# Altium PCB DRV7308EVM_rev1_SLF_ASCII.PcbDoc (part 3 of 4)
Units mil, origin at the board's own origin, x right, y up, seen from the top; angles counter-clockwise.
Board outline 6187 x 6000 mil, 4 copper layers (Top Layer, Ground, Power, Bottom Layer), stack 61.2 mil thick; 306 components, 128 nets, 676 pads, 1026 vias.
Unrouted connection lines stored in the file: 208.
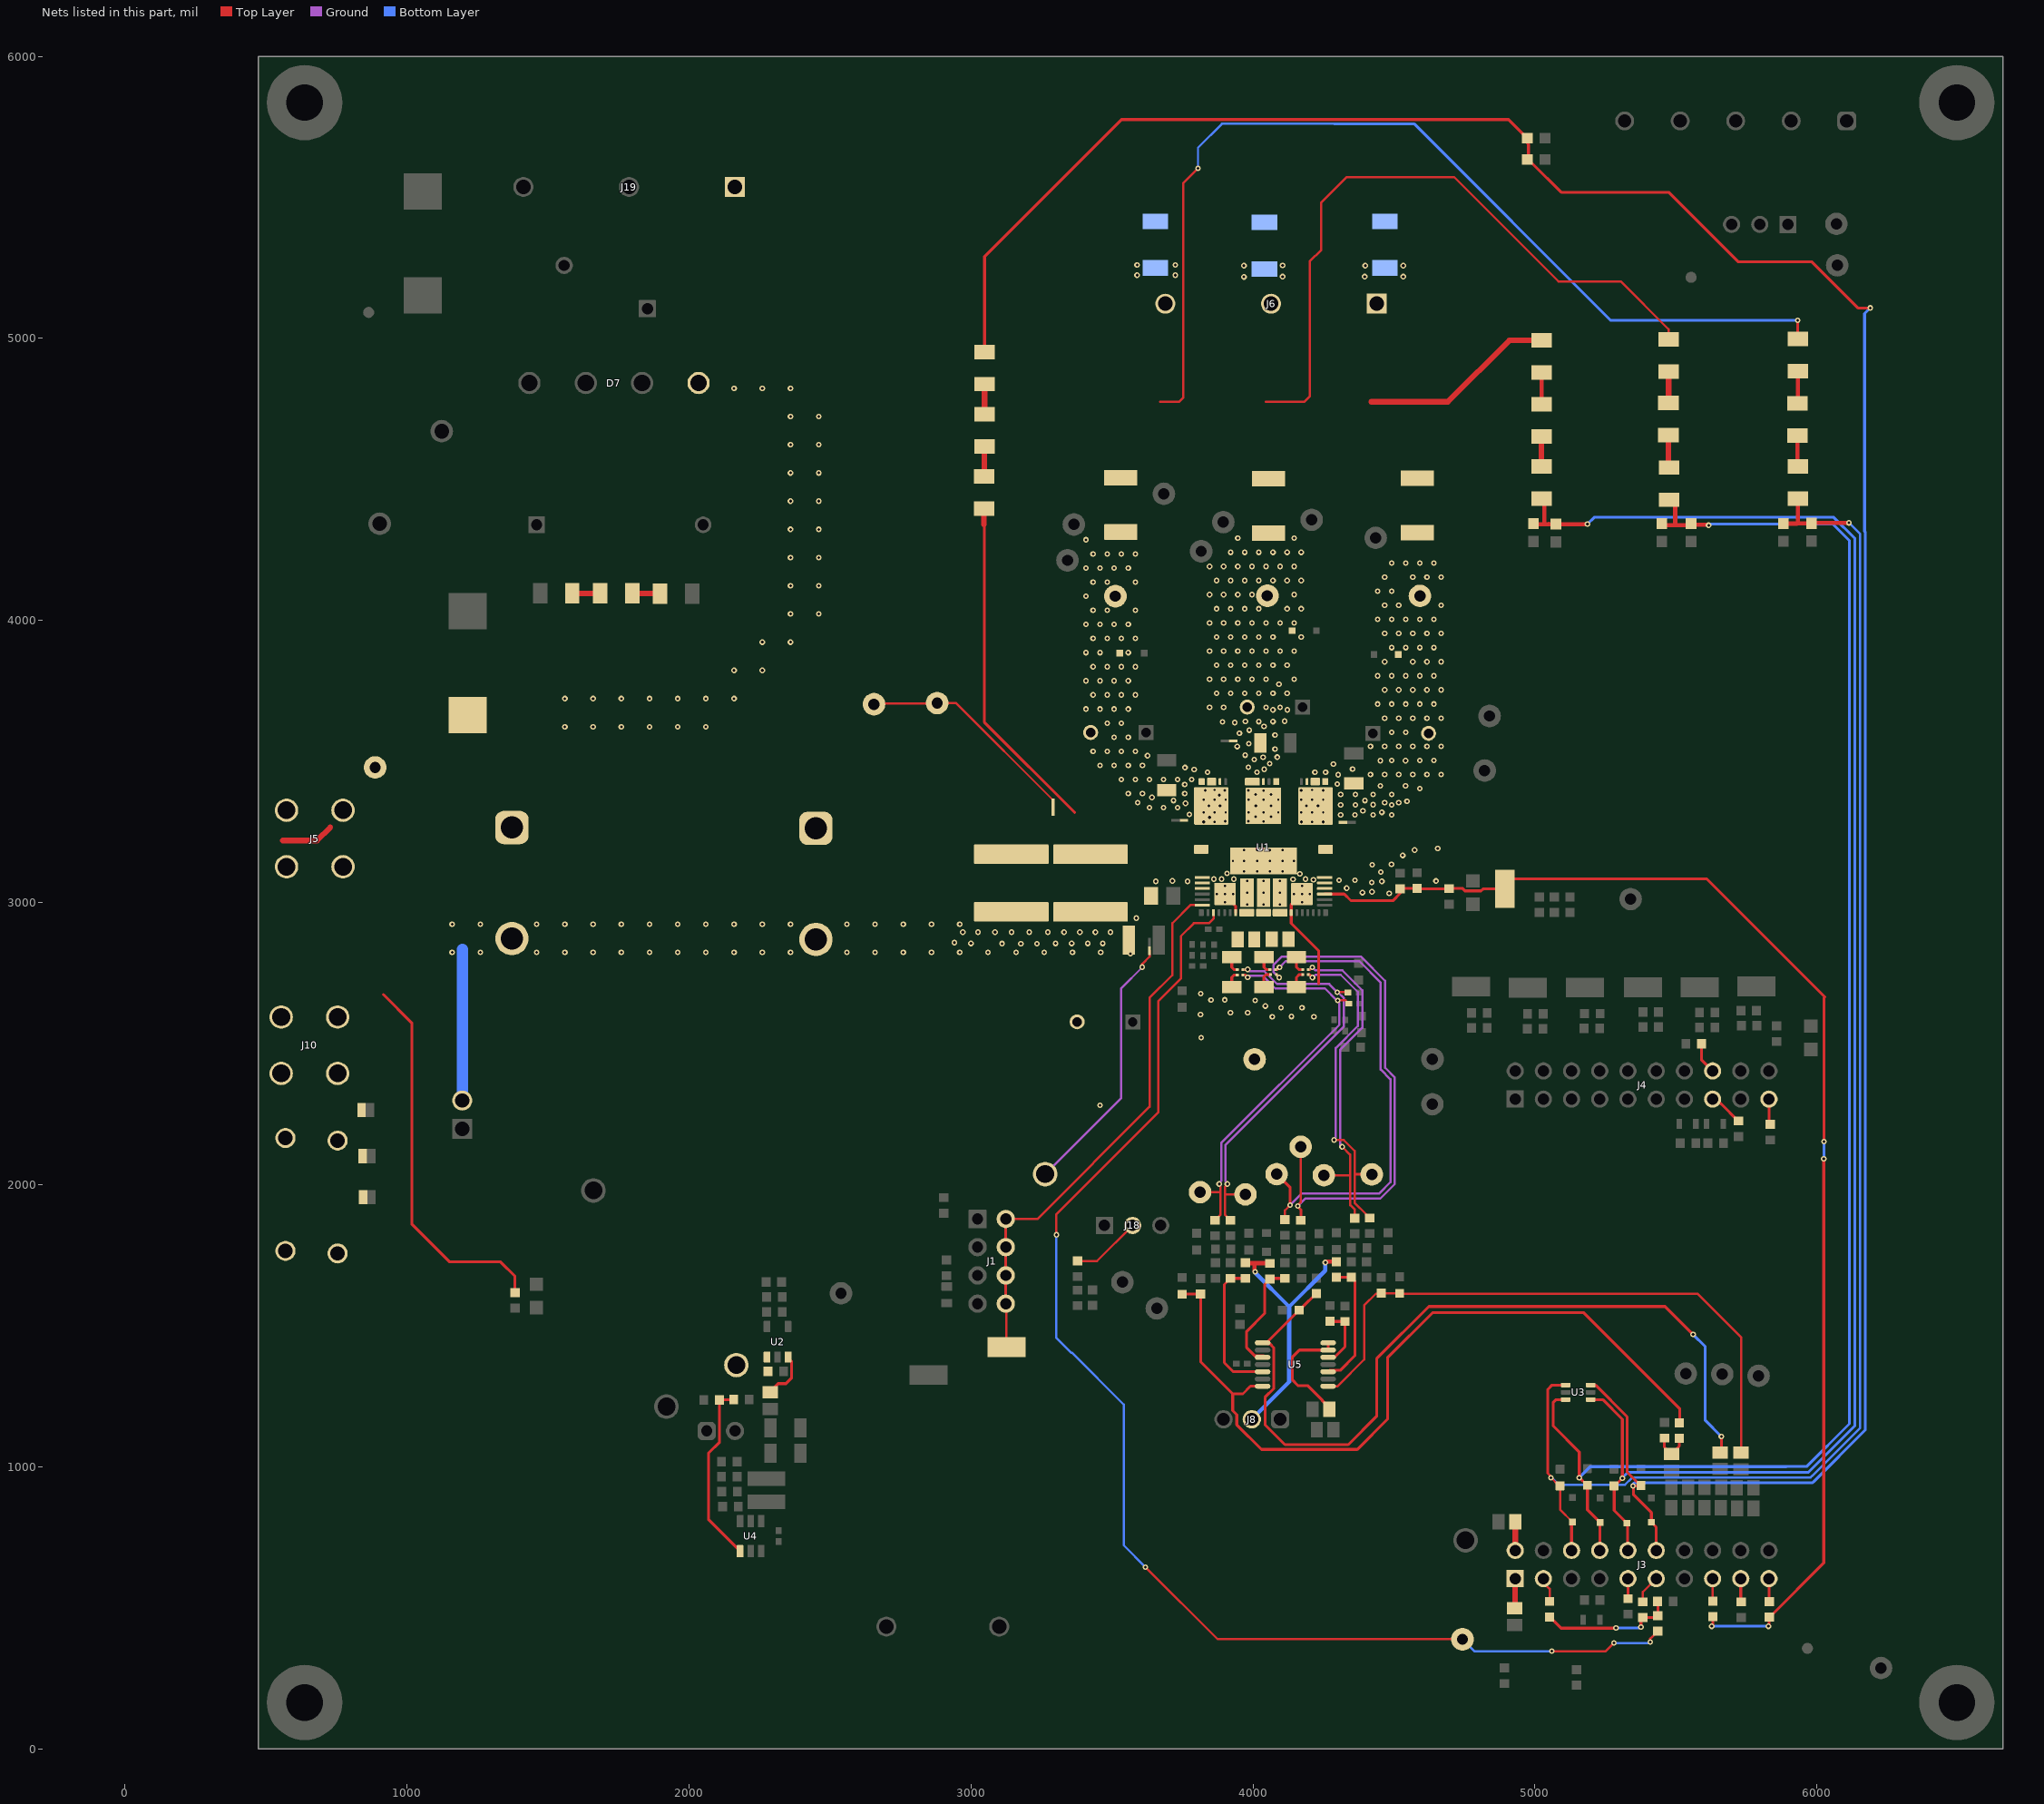
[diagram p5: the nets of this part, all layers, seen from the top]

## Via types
v1: diameter 20, hole 10, Top Layer to Bottom Layer, tented both sides, 933 vias
v2: diameter 19.68, hole 7.87, Top Layer to Bottom Layer, tented both sides, 57 vias
v3: diameter 39.37, hole 19.68, Top Layer to Bottom Layer, tented both sides, 24 vias
v4: diameter 20, hole 10, Top Layer to Bottom Layer, tented bottom, 12 vias

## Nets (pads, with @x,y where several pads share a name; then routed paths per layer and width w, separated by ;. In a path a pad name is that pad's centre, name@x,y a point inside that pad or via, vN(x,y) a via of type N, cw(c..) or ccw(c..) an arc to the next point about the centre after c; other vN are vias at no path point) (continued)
NetJ3_1: J3.1 R13.2 | length 105.7
  Top Layer w20: R13.2@4927.82,498.13 4929.82,500.13 J3.1@4929.82,603
NetJ3_2: J3.2 R36.1 | length 102.2
  Top Layer w20: J3.2@4929.82,703 4929.93,703.11 4929.93,804.59 R36.1@4930.35,805
NetJ3_3: J3.3 R135.2 | length 89.8
  Top Layer w8: J3.3@5029.82,603 5029.82,588.65 5051.7,566.77 R135.2@5051.7,522.25
NetJ3_9: J3.9 R2.2 | length 70.9
  Top Layer w10: J3.9@5329.82,603 5329.82,532.23 R2.2@5329.93,532.12
NetJ3_11: J3.11 R137.2 | length 101.8
  Top Layer w8: R137.2@5382.7,520.69 5382.7,555.88 J3.11@5429.82,603
NetJ3_15: J3.15 R48.2 | length 80.3
  Top Layer w8: J3.15@5629.82,603 5629.82,524.12 R48.2@5630.82,523.12
NetJ3_17: J3.17 R49.2 | length 82.9
  Top Layer w10: J3.17@5729.82,603 5729.82,521.56 R49.2@5730.82,520.56
NetJ3_19: J3.19 R50.2 | length 81.9
  Top Layer w10: J3.19@5829.82,603 5829.82,522.56 R50.2@5830.82,521.56
NetJ4_15: J4.15 R138.2 | length 124
  Top Layer w10: J4.15@5629.82,2303 5642.93,2303 5660.84,2285.09 5661.15,2285.09 5720.56,2225.69 5721.7,2225.69 R138.2@5721.64,2225.58
NetJ4_16: J4.16 R139.1 | length 112.1
  Top Layer w10: R139.1@5590.26,2498.69 5590.26,2442.56 J4.16@5629.82,2403
NetJ4_19: J4.19 R51.2 | length 91.5
  Top Layer w10: J4.19@5829.82,2303 5829.82,2218.56 R51.2@5834.82,2213.56
NetJ8_2: J8.2 R57.2 R63.2 R69.2 | length 998
  Top Layer w15: R63.2@3973.26,1722.7 3974.33,1721.63 4005.26,1721.63 ; v1(4007.26,1691.14) 4005.26,1693.14 4005.26,1721.63 ; R57.2@4060.56,1720.56 4059.49,1721.63 4005.26,1721.63 ; v1(4256.56,1724) 4259.12,1726.56 R69.2@4295.56,1726.56
  Bottom Layer w15: J8.2@3995.7,1168 4128.26,1300.56 4128.26,1566.91 ; v1(4007.26,1691.14) 4007.26,1687.91 4128.26,1566.91 ; v1(4256.56,1724) 4256.56,1695.21 4128.26,1566.91
NetJ18_2: J18.2 R118.2 | length 247.2
  Top Layer w8: R118.2@3378,1729 3447,1729 J18.2@3573,1855
NetNT12_1: NT12.1 TP40.1 TP41.1 | length 789.1
  Top Layer w8: TP41.1@2656,3703 2658,3705 2878,3705 TP40.1@2880,3707 2947,3707 3291,3363 NT12.1@3291,3353
NetNT13_1: NT13.1 TP50.1 | length 945.7
  Top Layer w8: v1(3607,2771) 3607,2782 3633,2808 NT13.1@3633,2829
  Ground w8: TP50.1@3263,2037 3532.84,2306.84 3532.84,2695.84 v1@3608,2771
NetR1_1: R1.1 R4.2 U4.4 | length 650.5
  Top Layer w10: R1.1@2158.44,1237.44 2108.56,1237.44 R4.2@2107.56,1236.44 2108.56,1235.44 2108.56,1087 2069,1047.44 2069,812.82 U4.4@2181.3,700.52
NetR14_1: R14.1 U5.13 U5.14 | length 421.7
  Top Layer w10: U5.14@4266.4,1438.92 U5.13@4266.4,1413.33 4164.78,1413.33 4139.06,1387.61 4139.06,1308.39 4160.73,1286.73 4194.92,1286.73 4245.17,1236.49 4245.17,1235.27 4270.53,1209.91 R14.1@4270.53,1204
NetR22_1: R22.1 R122.2 | length 98.7
  Top Layer w20: R22.1@1799.09,4096 1896.33,4096 R122.2@1897.33,4095
NetR22_2: R22.2 R121.1 | length 98.8
  Top Layer w20: R121.1@1586.09,4096 R22.2@1684.91,4096
NetR56_2: R56.2 R57.1 U5.3 | length 412.6
  Top Layer w10: U5.3@4034.12,1387.73 4038.85,1392.47 4006.77,1392.47 3977.56,1421.69 3977.56,1479.43 4041.26,1543.13 4041.26,1646.14 4048.83,1653.71 4048.83,1654.69 4059.57,1665.44 R57.1@4060.56,1665.44 4062.56,1667.44 R56.2@4113.56,1667.44
NetR62_2: R62.2 R63.1 U5.5 | length 563.1
  Top Layer w10: U5.5@4034.12,1336.55 3930.54,1336.55 3898.26,1368.84 3898.26,1645.59 R62.2@3920.26,1667.59 ; R62.2@3920.26,1667.59 R63.1@3973.26,1667.59 R62.2@3920.26,1667.59
NetR68_2: R68.2 R69.1 U5.10 | length 454.9
  Top Layer w10: U5.10@4266.4,1336.55 4271.13,1341.29 4309.43,1341.29 4361.26,1393.11 4361.26,1658.74 R68.2@4348.56,1671.44 R69.1@4295.56,1671.44
NetR70_2: R70.2 R78.1 R79.1 | length 134.8
  Top Layer w10: R78.1@5458.82,1101.44 5458.82,1069.53 R70.2@5483.82,1044.53 5511.82,1072.53 R79.1@5511.82,1100.44
NetR73_1: R73.1 R74.2 U5.12 | length 218.3
  Top Layer w10: U5.12@4266.4,1387.73 4289.01,1387.73 4326.26,1424.98 R74.2@4326.26,1514.59 4274.26,1514.59 R73.1@4273.26,1515.59
NetR91_1: R91.1 R98.2 | length 106.8
  Top Layer w20: R91.1@3047,4510.09 3047,4615.46 R98.2@3048,4616.46
NetR92_1: R92.1 R110.2 | length 115.9
  Top Layer w15: R110.2@5023.3,4766.91 R92.1@5023.3,4878.91
  Top Layer w20: R92.1@5023.3,4878.91 R92.1@5023.3,4882.85
NetR93_1: R93.1 R111.2 | length 115.6
  Top Layer w20: R111.2@5473,4767.03 5472.62,4767.41 5474,4768.79 R93.1@5474,4881.91
NetR94_1: R94.1 R112.2 | length 114.2
  Top Layer w15: R112.2@5931,4770.09 5932,4771.09 R94.1@5932,4883.91
NetR98_1: R98.1 R113.2 | length 112.6
  Top Layer w20: R113.2@3047,4841.85 R113.2@3048,4840.85 ; R98.1@3048,4726.69 R98.1@3048,4730.63 R113.2@3048,4837.91
NetR110_1: R110.1 R116.2 | length 110.2
  Top Layer w20: R116.2@5023,4546.61 5023,4656.38 R110.1@5023.3,4656.68
NetR111_1: R111.1 R130.2 | length 115.5
  Top Layer w20: R111.1@5473,4656.8 5473,4544.09 R130.2@5475,4542.09
NetR112_1: R112.1 R134.2 | length 114.2
  Top Layer w15: R134.2@5931,4543.15 R112.1@5931,4655.91
  Top Layer w20: R134.2@5931,4543.15 R134.2@5932,4542.15
nFAULT: R15.1 R41.1 R48.1 R50.1 R127.2 TP45.1 U1.26 | length 4560.6
  Top Layer w10: U1.26@4254.12,3030.04 4323.54,3030.04 4347.1,3006.48 4495.8,3006.48 4496,3006.28 4522,3032.28 R127.2@4522,3048.82 ; R127.2@4522,3050.44 R41.1@4582,3050.44 4583.46,3048.98 R15.1@4695,3048.98 ; R15.1@4695,3050.44 4742.1,3050.44 4751.41,3041.14 4808.59,3041.14 4815.45,3048 TP45.1@4893,3048 4893,3053.34 4923,3083.34 5609.73,3083.34 6028,2665.06 6025,2662.06 v1(6025,2152.69) ; v1(5626.82,434) 5630.82,438 R48.1@5630.82,468 ; v1(5827.82,434) 5830.82,437 R50.1@5830.82,466.44 5831.8,466.44 6024,658.64 v1(6024,2091.69)
  Bottom Layer w10: v1(5626.82,434) v1(5827.82,434) ; v1(6024,2091.69) 6025,2092.69 v1(6025,2152.69)
OUT_A: C62.1 J6.3 L2.2 R94.2 | length 3506.6
  Top Layer w8: 3670.2,4775 3737,4775 3753,4791 3753,5551 v1(3805,5603)
  Top Layer w10: R94.2@5932,5004.3 v1(5932,5064)
  Bottom Layer w8: v1(3805,5603) 3805,5676 3890,5761 4288,5761
  Bottom Layer w10: 4288,5761 4571,5761 5268,5064 v1(5932,5064)
  other v4: 3589,5224 3725,5224 3589,5260 3725,5260
OUT_B: C63.1 J6.2 L3.2 R93.2 | length 2397.7
  Top Layer w8: 4045,4775 4182,4775 4201.09,4794.09 4201.09,5273.09 4242,5314 4242,5482 4332,5572 4713,5572 5083,5202 5304,5202 5474,5032 R93.2@5474,4996.09
  other v4: 3968,5218 4105,5219 3968,5258 4105,5259
OUT_C: C64.1 J6.1 L4.2 R92.2 | length 693.8
  Top Layer w20: 4419.8,4775 4691,4775 4909.09,4993.09 R92.2@5023.3,4993.09
  other v4: 4396,5219 4533,5219 4398,5258 4533,5258
OUTA: C1.1 C59.2 D14.2 L2.1 NT9.1 TP1.1 U1.49 U1.50 U1.51 U1.52 U1.53 U1.54 U1.55 U1.56 U1.57 U1.@3851.96,3342.48 U1.@3853.37,3428.66
  other v1: 3825.14,3285.83 3901.5,3287.8 3846,3302 3774,3312.29 3632.84,3336 3682.84,3336 3732.84,3336 3843.33,3342.48 3883,3343 3760.72,3351.56 3591.15,3353.7 3718,3361.58 3641.84,3372.5 3880.5,3380.58 3557.84,3386 3607.84,3386 3757.84,3386 3831.28,3397.17 3900,3397.17 3757.84,3418.82 3532.84,3436 3582.84,3436 3632.84,3436 3682.84,3436 3732.84,3436 3782.84,3436 3838.7,3462 3791.29,3471.5 3758.89,3478.54 3457.84,3486 3507.84,3486 3557.84,3486 3607.84,3486 3625.88,3520.75 3432.84,3536 3482.84,3536 3532.84,3536 3582.84,3536 3507.84,3586 3557.84,3586 3482.84,3636 3532.84,3636 3407.84,3686 3457.84,3686 3507.84,3686 3557.84,3686 3432.84,3736 3482.84,3736 3532.84,3736 3582.84,3736 3407.84,3786 3457.84,3786 3507.84,3786 3557.84,3786 3432.84,3836 3482.84,3836 3532.84,3836 3582.84,3836 3407.84,3886 3457.84,3886 3557.84,3886 3432.84,3936 3482.84,3936 3532.84,3936 3582.84,3936 3407.84,3986 3457.84,3986 3507.84,3986 3557.84,3986 3432.84,4036 3482.84,4036 3582.84,4036 3407.84,4086 3432.84,4136 3482.84,4136 3582.84,4136 3407.84,4186 3457.84,4186 3507.84,4186 3557.84,4186 3432.84,4236 3482.84,4236 3532.84,4236 3582.84,4236 3407.84,4286
  other v2: 3864.12,3285.83 3825.14,3319.84 3864.12,3319.84 3903.09,3319.84 3825.14,3365.12 3864.12,3365.12 3903.09,3365.12 3864.12,3399.13
OUTB: C3.1 C60.2 D16.2 L3.1 NT10.1 TP2.1 U1.42 U1.44 U1.45 U1.46 U1.47 U1.72 U1.@3997.7,3428.66
  other v1: 3984,3287.8 4009.9,3304.29 4064.38,3304.29 4010.01,3342.48 4064,3342.48 4009.9,3383 4064.38,3383 3984,3397.17 4014,3462 4039.76,3472.32 3984,3480 4059.3,3492.63 4004.53,3506.56 4036,3515.15 4086,3515.5 3972,3522.45 4078,3544 3944,3553 3985,3563 4078,3594 3952,3600 3986.85,3611.01 4039,3624.01 3935.07,3638.1 3892.2,3640.46 3973.21,3642 4021,3641.51 4071,3641.51 4112,3643 4070.98,3683 4122.12,3683 3846,3691.51 3896,3691.51 4046,3691.51 4096,3691.51 3871,3741.51 3921,3741.51 3971,3741.51 4021,3741.51 4071,3741.51 4121,3741.51 4092,3773.7 3846,3791.51 3896,3791.51 3946,3791.51 3996,3791.51 4046,3791.51 4146,3791.51 3871,3841.51 3921,3841.51 3971,3841.51 4021,3841.51 4071,3841.51 4121,3841.51 3846,3891.51 3896,3891.51 3946,3891.51 3996,3891.51 4046,3891.51 4096,3891.51 4146,3891.51 3871,3941.51 3921,3941.51 3971,3941.51 4021,3941.51 4071,3941.51 4171,3941.51 3846,3991.51 3896,3991.51 3946,3991.51 3996,3991.51 4046,3991.51 4096,3991.51 4146,3991.51 3871,4041.51 3921,4041.51 3971,4041.51 4021,4041.51 4121,4041.51 4171,4041.51 3846,4091.51 3896,4091.51 3946,4091.51 3996,4091.51 4146,4091.51 3871,4141.51 3921,4141.51 3971,4141.51 4021,4141.51 4071,4141.51 4121,4141.51 4171,4141.51 3846,4191.51 3896,4191.51 3946,4191.51 3996,4191.51 4046,4191.51 4096,4191.51 4146,4191.51 3921,4241.51 3971,4241.51 4021,4241.51 4071,4241.51 4121,4241.51 4171,4241.51 3946,4291.51 4146,4291.51
  other v2: 4037.07,3287.8 3984.39,3319.84 4037.07,3319.84 4089.75,3319.84 3984.39,3365.12 4037.07,3365.12 4089.75,3365.12 4037.07,3397.17
OUTC: C5.1 C61.2 D15.2 L4.1 NT11.1 TP3.1 U1.32 U1.33 U1.34 U1.35 U1.36 U1.37 U1.38 U1.39 U1.40 U1.@4220.77,3428.66 U1.@4222.18,3342.48
  other v1: 4171.56,3285.83 4249,3285.83 4311,3311 4361.77,3311 4426,3311 4492,3311 4457,3319.84 4389.76,3325.32 4188.88,3342.48 4230.61,3342.48 4311,3346 4363,3346 4492,3346 4426,3347 4466.77,3353.7 4516.77,3353.7 4546,3359 4396.52,3361.58 4311,3383 4363,3383 4426,3383 4492,3383 4249,3397.17 4171.05,3397.85 4591.77,3403.7 4452,3414 4541,3414 4299,3420 4302,3453 4416.77,3453.7 4466.77,3453.7 4516.77,3453.7 4566.77,3453.7 4616.77,3453.7 4666.77,3453.7 4219.39,3462.08 4257.56,3462.08 4353,3473 4285.07,3491.1 4452,3503 4541,3503 4491.77,3503.7 4591.77,3503.7 4641.77,3503.7 4416.77,3553.7 4466.77,3553.7 4516.77,3553.7 4566.77,3553.7 4616.77,3553.7 4666.77,3553.7 4491.77,3603.7 4541.77,3603.7 4466.77,3653.7 4516.77,3653.7 4566.77,3653.7 4616.77,3653.7 4666.77,3653.7 4441.77,3703.7 4491.77,3703.7 4541.77,3703.7 4591.77,3703.7 4641.77,3703.7 4466.77,3753.7 4516.77,3753.7 4566.77,3753.7 4616.77,3753.7 4666.77,3753.7 4441.77,3803.7 4491.77,3803.7 4541.77,3803.7 4591.77,3803.7 4641.77,3803.7 4466.77,3853.7 4566.77,3853.7 4616.77,3853.7 4666.77,3853.7 4491.77,3903.7 4541.77,3903.7 4591.77,3903.7 4641.77,3903.7 4466.77,3953.7 4516.77,3953.7 4566.77,3953.7 4616.77,3953.7 4666.77,3953.7 4441.77,4003.7 4491.77,4003.7 4541.77,4003.7 4591.77,4003.7 4641.77,4003.7 4466.77,4053.7 4516.77,4053.7 4666.77,4053.7 4441.77,4103.7 4491.77,4103.7 4466.77,4153.7 4566.77,4153.7 4616.77,4153.7 4666.77,4153.7 4491.77,4203.7 4541.77,4203.7 4591.77,4203.7 4641.77,4203.7
  other v2: 4210.02,3285.83 4171.05,3319.84 4210.02,3319.84 4249,3319.84 4171.05,3365.12 4210.02,3365.12 4249,3365.12 4210.02,3399.13
PE: J19.1
PGND: C6.1 C8.1 C9.1 C10.1 C57.2 C58.2 C62.2 C63.2 C64.2 C67.2 D7.4 J9.2 J10.1 NT1.2 NT2.2 NT4.1 NT6.1 NT8.1 NT14.2 R3.1 R6.1 R16.1 R37.1 TP12.1 TP12.2 TP13.1 TP13.2 TP17.1 U1.7 U1.17 U1.27 U1.28 U1.29 U1.60 U1.61 U1.62 U1.66 U1.70 U1.71 | length 2575.3
  Top Layer w10: 916.49,2673.51 1017,2573 1017,2381.22 1016.78,2381 1016.78,1860.22 1151.3,1725.7 1332.3,1725.7 1383,1675 R16.1@1383,1617 ; R3.1@3925,2699.85 3925,2735 3933,2743 NT6.1@3944,2743 ; U1.66@3933,2993 3938.65,2987.35 U1.7@3938.65,2964.09 ; U1.71@4000.69,3150.51 4113.92,3150.51 U1.71@4135.5,3128.94 ; R6.1@4038.82,2699.85 4038.82,2737.71 4046.11,2745 NT4.1@4063,2745 ; U1.70@4139,2996 4135.5,2992.5 U1.17@4135.5,2964.09 4135.5,2926.34 4233,2828.84 4233,2713.33 4233.33,2713 ; R37.1@4154,2699.85 4154,2735 4163,2744 NT8.1@4176,2744
  Bottom Layer w40: J9.2@1196,2298 1196,2834
  other v1: 3458,2281 3816,2521 4068.34,2595 4216,2595 4136,2596 3814,2603 3920.19,2609 3981,2609 4099,2627 4174,2627 4044,2633 4008,2653 3851.06,2654 3899.63,2655 3815,2677 3565,2819 1160,2823 1260,2823 1460,2823 1560,2823 1660,2823 1760,2823 1860,2823 1960,2823 2060,2823 2160,2823 2260,2823 2360,2823 2560,2823 2660,2823 2760,2823 2860,2823 2960,2823 3060,2823 3160,2823 3260,2823 3360,2823 3460,2823 3177,2853.69 3234,2854 3000,2855 3110,2854.42 3300,2855 3357,2855 3414,2855 3467,2855 2941,2858 2971,2895 3025,2895 3085,2895 3144,2895 3207,2895 3273,2895 3330,2895 3386,2895 3441,2895 3495,2895 1160,2923 1260,2923 1460,2923 1560,2923 1660,2923 1760,2923 1860,2923 1960,2923 2060,2923 2160,2923 2260,2923 2360,2923 2560,2923 2660,2923 2760,2923 2860,2923 2960,2923 3586,2944.87 4483,3032.28 4388,3035 4422,3038 4332.08,3051 4421,3071.19 3655,3075 3768.35,3075 4457,3075 3714,3076.76 4649,3076.38 4304.85,3079 4362,3078.71 4214.24,3081 4141.99,3082 3861,3083 3888.57,3083 3932,3083.19 4186,3083 4166,3102 3908,3103 4453,3107.81 4423,3134 4491,3135 4531,3167 4573,3186 4655,3192 1560,3623 1660,3623 1760,3623 1860,3623 1960,3623 2060,3623 1560,3723 1660,3723 1760,3723 1860,3723 1960,3723 2060,3723 2160,3723 2160,3823 2260,3823 2260,3923 2360,3923 2360,4023 2460,4023 2360,4123 2460,4123 2360,4223 2460,4223 2360,4323 2460,4323 2360,4423 2460,4423 2360,4523 2460,4523 2360,4623 2460,4623 2360,4723 2460,4723 2160,4823 2260,4823 2360,4823
  other v2: 3900.65,3001.14 4173.49,3001.14 3872.31,3030.2 3900.65,3030.2 3929,3030.2 4145.14,3030.2 4173.49,3030.2 4201.83,3030.2 3900.65,3059.21 4173.49,3059.21 3968.57,3110.24 4014.24,3110.24 4059.91,3110.24 4105.57,3110.24 3928.8,3147.83 3968.57,3147.83 4014.24,3147.83 4059.91,3147.83 4105.57,3147.83 4145.34,3147.83 3968.57,3185.43 4014.24,3185.43 4059.91,3185.43 4105.57,3185.43
SLA: NT5.1 R3.2 R5.2 U1.8 U1.9 U1.10 U1.67 U1.@3978.02,2964.09 | length 76.4
  Top Layer w8: R3.2@3925,2806.15 R3.2@3942.93,2806.15
  Top Layer w10: R3.2@3925,2806.15 3925,2770 3933,2762 NT5.1@3944,2762
  other v2: 3979,2993.66 3979,3035 3979,3076.38
SLB: NT3.1 R5.1 R6.2 R21.2 U1.11 U1.12 U1.13 U1.68 U1.@4037.07,2964.09 | length 60.5
  Top Layer w10: R6.2@4038.82,2806.15 4039,2805.97 4039,2770 4047,2762 NT3.1@4060,2762
  other v2: 4037.07,2993.66 4037.07,3035 4037.07,3076.38
SLC: NT7.1 R21.1 R37.2 U1.14 U1.15 U1.16 U1.69 U1.@4096.13,2964.09 | length 60.9
  Top Layer w10: R37.2@4154,2806.15 4154,2771 4163,2762 NT7.1@4176,2762
  other v2: 4095.14,2993.66 4095.14,3035 4095.14,3076.38
SLEW: J1.2 J1.4 J1.6 J1.8 TP24.1 U1.65 | length 1946.6
  Top Layer w8: J1.8@3123.23,1578 3126,1575.23 TP24.1@3126,1424 ; J1.2@3123.23,1878 3235,1878 3633,2276 3633,2661.79 3714,2742.79 3714,2926.73 3777.94,2990.67 U1.65@3820.02,2990.67
  Top Layer w10: J1.8@3123.23,1578 J1.6@3123.23,1678 J1.4@3123.23,1778 J1.2@3123.23,1878
SNA: NT6.2 R11.1 R59.1 TP31.1 | length 1464.2
  Top Layer w8: TP31.1@3812.26,1973.14 3884.26,1973.14 3885.26,1972.14 ; R59.1@3865.26,1873.7 3885.26,1893.7 3885.26,1972.14 ; v1(3880,2002) 3880,1998.75 3885.26,1993.5 3885.26,1972.14 ; NT6.2@3964,2743 3973,2743 v1(3981,2735) ; v1(4300,2653) 4328.32,2653 R11.1@4339.32,2642
  Ground w8: v1(3880,2002) 3880,2005.15 3887.54,2012.69 3887.54,2147.54 4306,2566 4306,2643.75 4300,2649.75 v1(4300,2653) 4297.65,2653 4255.11,2695.54 4079.25,2695.54 4033.79,2741 3987,2741 v1(3981,2735)
SNB: NT4.2 R52.1 TP14.1 | length 1891.1
  Top Layer w8: NT4.2@4083,2745 4093,2735 v1(4093,2734) ; v1(4159.35,1924.36) 4159.35,1927.61 4169.19,1937.45 TP14.1@4169.19,2134
  Top Layer w10: v1(4159.35,1924.36) 4159.35,1921.66 4170.12,1910.89 4170.12,1874.12 R52.1@4169.56,1873.56
  Ground w8: v1(4093,2734) 4072.54,2754.46 4072.54,2778.89 4101.03,2807.38 4383.48,2807.38 4468.53,2722.33 4468.53,2414.33 4503,2379.86 4503,2002.07 4450.83,1949.9 4184.89,1949.9 v1(4159.35,1924.36)
SNC: NT8.2 R65.1 TP54.1 | length 1178.6
  Top Layer w8: v1(4287.54,2158.21) 4321.48,2158.21 4360.26,2119.44 4360.26,1935.3 4401.27,1894.29 4401.27,1893.31 4413.02,1881.56 R65.1@4414,1881.56
  Top Layer w10: NT8.2@4196,2744 4201,2744 v1(4211,2734) ; 4361.26,2037.14 4362.26,2036.14 TP54.1@4421.26,2036.14
  Ground w8: v1(4211,2734) 4212.15,2734 4221.69,2743.54 4311,2743.54 4372,2682.54 4372,2562.4 4293.54,2483.94 4293.54,2167.46 4287.54,2161.46 v1(4287.54,2158.21)
SOA: C24.2 R58.2 R79.2 U5.7 | length 2825.3
  Top Layer w10: C24.2@3749,1611.47 3814.14,1611.47 R58.2@3814.26,1611.59 3814.26,1372.1 3928.02,1258.34 ; U5.7@4034.12,1285.37 3991.3,1285.37 3964.27,1258.34 3928.02,1258.34 ; R79.2@5511.82,1155.56 5512.82,1156.56 5512.82,1206 5173.24,1545.57 4636.51,1545.57 4477,1386.06 4477,1168 4370,1061 4030.08,1061 3942.62,1148.46 3942.62,1183.98 3928.02,1198.58 3928.02,1258.34
SOB: C17.2 R46.2 R71.2 U5.1 | length 2951.9
  Top Layer w10: U5.1@4034.12,1438.92 4050.73,1438.92 4054.29,1442.48 4054.29,1445.76 C17.2@4163.53,1555 4174.28,1565.75 4176.32,1565.75 4224.02,1613.44 R46.2@4225,1613.44 ; U5.1@4054.9,1438.92 4054.36,1438.37 4054.36,1435.42 4060.22,1435.42 4073.67,1421.96 4073.67,1276.73 4042.77,1245.83 4042.77,1148.51 4113.28,1078 4338,1078 4438.26,1178.26 4438.26,1382.5 4623.55,1567.78 5461.47,1567.78 v1(5560.84,1468.41) ; R71.2@5656.82,1050.53 5660.82,1054.53 v1(5660.82,1107)
  Bottom Layer w10: v1(5560.84,1468.41) 5603.71,1425.54 5603.71,1164.1 v1(5660.82,1107)
SOC: C50.2 R64.2 R72.2 U5.8 | length 2183.2
  Top Layer w8: U5.8@4266.4,1285.37 4300.19,1285.37 4394.26,1379.44 4394.26,1571.59 4436.26,1613.59 4453.14,1613.59 R64.2@4455,1615.44 ; R64.2@4459.11,1614.47 C50.2@4520,1614.47 ; C50.2@4520,1613.59 5576.35,1613.59 5730.82,1459.12 R72.2@5730.82,1049.53
SPA: NT5.2 R9.1 R61.1 TP47.1 | length 1495.6
  Top Layer w8: v1(3909,2002) 3909,2000.06 3900.26,1991.31 3900.26,1966.14 ; R61.1@3920.26,1873.7 3900.26,1893.7 3900.26,1966.14 ; NT5.2@3964,2762 3976.56,2762 3977.56,2763 v1(3981,2763) ; TP47.1@3973.26,1965.14 3901.26,1965.14 3900.26,1966.14 ; v1(4299,2682) R9.1@4333.24,2682 ; R9.1@4333.24,2682 4337,2678.24 R9.1@4337,2681 4336,2682 R9.1@4333.24,2682
  Ground w8: v1(3909,2002) 3909,2005.25 3903,2011.25 3903,2141.14 4321.46,2559.6 4321.46,2661.89 4301.35,2682 v1(4299,2682) 4270,2711 4085.65,2711 4040.19,2756.46 3987.54,2756.46 v1(3981,2763)
SPB: NT3.2 R55.1 TP48.1 | length 1717
  Top Layer w8: NT3.2@4080,2762 4086,2762 v1(4094,2770) ; R55.1@4113.56,1875.56 4113.56,1908.92 v1(4131.85,1927.21)
  Top Layer w10: TP48.1@4083.96,2037.14 4131.85,1989.25 v1(4131.85,1927.21)
  Ground w8: v1(4094,2770) 4115.92,2791.92 4377.08,2791.92 4453.07,2715.93 4453.07,2407.93 4487.54,2373.46 4487.54,2008.47 4448.06,1968.99 4173.63,1968.99 v1(4131.85,1927.21)
SPC: NT7.2 R67.1 TP49.1 | length 1167.7
  Top Layer w8: NT7.2@4196,2762 4202,2762 v1(4210,2770) ; TP49.1@4271.13,2033.14 4343.26,2033.14 4345.26,2035.14 ; v1(4316,2134) 4343.86,2106.14 4345.26,2106.14 4345.26,2035.14 ; R67.1@4356,1880.56 R67.1@4356,1881.12 ; R67.1@4361,1881.12 4361,1911.47 4345.26,1927.21 4345.26,2035.14
  Ground w8: v1(4210,2770) 4221,2759 4317.4,2759 4387.46,2688.94 4387.46,2556 4309,2477.54 4309,2139 4314,2134 v1(4316,2134)
VM: C6.2 C8.2 C57.1 C58.1 F2.2 J5.1 NT12.2 R91.2 TP35.1 U1.30 U1.31 U1.58 U1.59 U1.@3816.59,3188.5 U1.@4257.56,3188.5 | length 1396.8
  Top Layer w10: 3047,4340.69 3047,3640 3367.34,3319.66
  Top Layer w20: 560,3220 681.06,3220 728,3266.94 ; 3046,4340.69 3046,4394.91 R91.2@3047,4395.91
VREF_IN: C55.1 R7.2 TP19.1 U2.1 U2.3 | length 177.6
  Top Layer w10: R7.2@2288,1263.97 2288,1266.37 2316,1294.37 2343.49,1294.37 2364,1314.88 2364,1372.44 2351.4,1385.04 U2.3@2351.4,1388.76
VSENA: C13.2 D12.1 J3.6 R105.2 R106.2 R134.1 U3.1 | length 5410.9
  Top Layer w8: v1@5056.42,961.27 5084.25,933.44 C13.2@5085.23,933.44 ; C13.2@5089,933.44 5089,847.51 D12.1@5132.82,803.69
  Top Layer w10: v1@5059.82,960.9 5059.82,961.93 5045.09,976.66 5045.09,1273.38 5060.68,1288.97 U3.1@5108.79,1288.97 ; J3.6@5129.82,703 5129.82,800.69 D12.1@5132.82,803.69
  Top Layer w15: R106.2@5881,4343.5 5928.29,4343.5 5932,4347.21 ; R134.1@5932,4431.91 5932,4347.21 ; v1(6113.07,4346.07) 5989.36,4346.07 5988,4344.71 5934.5,4344.71 5932,4347.21
  Bottom Layer w8: v1@5059.82,960.9 5084.73,935.98 5319.47,935.98 5344.47,960.98 5976.22,960.98 5982.07,966.84 5982.38,966.84 6153,1137.46 6153,4306.13 v1(6113.07,4346.07)
  other v1: 5056.05,960.9
VSENB: C15.2 D11.1 J3.8 R103.2 R104.2 R130.1 U3.3 | length 5615
  Top Layer w10: U3.3@5108.79,1237.79 5074.5,1237.79 5065,1228.3 5065,1143.96 5157.06,1051.9 v1(5157.06,960.98) ; v1@5157.27,961.19 5185.02,933.44 5186,933.44 5186,846.82 D11.1@5230.82,802 5230.82,704 J3.8@5229.82,703
  Top Layer w15: R103.2@5449.27,4343.02 5454.19,4338.1 5497,4338.1 ; R130.1@5475,4427.91 5478.91,4427.91 5497,4409.82 5497,4338.1 ; v1(5615.69,4337.6) 5614.18,4339.1 5553.69,4339.1 5552.69,4338.1 5497,4338.1
  Bottom Layer w10: v1(5157.06,960.98) 5196.07,1000 5891.45,1000 5891.62,1000.17 5963.08,1000.17 6115,1152.09 6115,4283.32 6056.76,4341.56 5606,4341.56
VSENC: C34.2 D10.1 J3.10 R101.2 R102.2 R116.1 U3.4 | length 5967.8
  Top Layer w10: U3.4@5195.79,1236.21 U3.4@5197.38,1237.79 5240.13,1237.79 5309.73,1168.2 5309.73,959.19 5281.98,931.44 5281,931.44 5281,844.51 D10.1@5325.82,799.69 5327.82,797.69 5327.82,705 J3.10@5329.82,703
  Top Layer w15: R102.2@4995,4339.09 4996.47,4340.56 5033,4340.56 ; R116.1@5023,4432.44 5033,4422.44 5033,4340.56 ; 5049,4341.56 5048.5,4341.06 ; v1(5186,4341.56) 5185.5,4341.06 5048.5,4341.06 ; 5033,4340.56 5048,4340.56 5048.5,4341.06
  Bottom Layer w10: v1(5186,4341.56) 5210,4365.56 6059.63,4365.56 6134,4291.19 6134,1143.91 ; v1(5309.94,958.98) 5309.94,960.9 5329.02,979.98 5969.75,979.98 6133.84,1144.07
VSENVM: C14.2 D9.1 J3.12 R99.2 R100.2 R113.1 U3.6 | length 9622.7
  Top Layer w10: R113.1@3048,4952.09 3048,5290 3534,5776 4906.5,5776 4957.82,5724.69 4957.82,5723.7 4971.52,5710 R99.2@4972.5,5710 ; R99.2@4966.13,5698.73 4976.88,5687.98 4976.88,5634 4976.88,5633.02 4987.63,5622.27 4988.61,5622.27 5092.88,5518 5474,5518 5720,5272 5981,5272 6145.05,5107.95 v1(6189,5107.95) ; U3.6@5197.38,1288.97 5214.44,1288.97 5326.73,1176.68 5326.73,980.72 5375.02,932.44 5376,932.44 5375.56,932 v1(5348.01,932) 5349.63,930.38 5349.63,900.18 5412.82,836.99 D9.1@5412.82,802.69 5429.82,785.69 J3.12@5429.82,703
  Bottom Layer w10: v1(5348.01,932) 5344.47,935.53 5351.93,942.98 5983.67,942.98 5986.29,945.6 5986.6,945.6 6171,1130 6171,4313.59 6168.97,4315.61 6168.97,5087.93 v1(6189,5107.95)
VTEMP: R120.1 TP46.1 U1.3 | length 4688.3
  Top Layer w8: v1(3303,1822) 3303,1895.13 3663.57,2255.71 3663.57,2649.93 3744,2730.36 3744,2880.34 3789.94,2926.28 3843.33,2926.28 3859.91,2942.86 U1.3@3859.91,2964.09 ; v1(3618.8,644.12) 3874.92,388 TP46.1@4742.82,388 TP46.1@4741.13,389.69 ; v1(5059.82,346) 5250.82,346 v1(5279.82,375) ; v1(5408.7,378.13) 5408.7,389.57 R120.1@5435.7,416.57
  Bottom Layer w8: v1(3303,1822) 3303,1456 3356,1403 3359,1403 3541.98,1220.02 3541.98,720.93 v1(3618.8,644.12) ; TP46.1@4742.82,388 4784.82,346 v1(5059.82,346) ; v1(5279.82,375) 5400.82,375 v1@5403.82,378
VTEMP_IN: C53.1 R120.2 R135.1 R137.1 | length 486.5
  Top Layer w10: R135.1@5051.7,467.13 5052.68,467.13 5092.53,427.28 5286.44,427.28 v1(5287.31,428.15) ; v1(5375.7,431.69) 5375.7,458.57 R137.1@5382.7,465.57 5429.58,465.57 R120.2@5435.7,471.69 5435.7,520.57 C53.1@5434.58,521.69 ; C53.1@5429.82,522.44 C53.1@5430.82,521.44
  Bottom Layer w10: v1(5287.31,428.15) 5372.16,428.15 v1(5375.7,431.69)
pads on no net: FID1.1 FID2.1 FID3.1 H9.0 H10.0 H11.0 H12.0 H13.0 H14.0 H15.0 H16.0 J3.5 J3.13 J3.20 J4.6 J4.8 J4.10 J4.12 J4.14 J4.17 J4.18 MH5.1 MH6.1 MH7.1 MH8.1 SH-J1.0 SH-J2.0 SH-J3.0 SH-J4.0 SH-J5.0 U1.1 U1.23 U2.4
copper on no net:
  other v3: 637,64.59 6496,64.59 550.91,114.3 723.09,114.3 6409.91,114.3 6582.09,114.3 550.91,213.7 723.09,213.7 6409.91,213.7 6582.09,213.7 637,263.41 6496,263.41 637,5736.59 6496,5736.59 550.91,5786.3 723.09,5786.3 6409.91,5786.3 6582.09,5786.3 550.91,5885.7 723.09,5885.7 6409.91,5885.7 6582.09,5885.7 637,5935.41 6496,5935.41

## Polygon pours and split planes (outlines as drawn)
VM on Top Layer "TOP_LAYER_VM_P328" (solid, remove dead copper, pour order 328): 1283,3731 1283,3531 1414,3400 1426.84,3400 1426.84,3373 862,3373 844,3391 844,3652 924,3732
NetF2_1 on Top Layer "TOP_LAYER_NETF2_1_P325" (solid, remove dead copper, pour order 325): 1284,3967 1284,4098 998,4384 876,4384 782,4290 782,3969 1280,3969 1282,3967
PGND on Top Layer "TOP_LAYER_PGND_P324" (solid, remove dead copper, pour order 324): 1143.57,2758.5 843,2457.93 843,2758.5
VM on Top Layer "TOP_LAYER_VM_P322" (solid, remove dead copper, pour order 322): 755,3414 532,3414 532,3108 557,3083 814,3083 931,3200 2950,3200 3012,3138 3557.15,3138 3591.15,3172 3838.7,3172 3838.7,3204.3 3838,3205 3490.15,3205 3295.15,3400 769,3400
NetD7_1 on Top Layer "TOP_LAYER_NETD7_1_P320" (solid, remove dead copper, pour order 320): 1472.18,4823.72 1472.18,4855.14 1472.18,4859.82 1422.28,4909.72 952.18,4909.72 889.18,4846.72 889.18,4562.72 1154.18,4562.72 1388.18,4796.72 1445.18,4796.72 1449.18,4800.72
GND on Top Layer "TOP_LAYER_GND_P317" (solid, remove dead copper, pour order 317): 5017,5810 6125,5810 6139,5796 6139,5676 6376,5439 6376,46 1000,46 1000,390 599,791 599,1644 857,1902 857,2558 1007,2558 1007,2348 1130,2225 1137,2232 2981,2232 3167,2046 3167,1952 3169,1950 3169,1853 4367,1853 4369,1855 4359,1865 4359,2819 4574,3034 6226,3034 6226,5251 5923,5554 5022,5554 5017,5559
NetF1_2 on Top Layer "TOP_LAYER_NETF1_2_P315" (solid, remove dead copper, pour order 315): 1454.03,5586.09 989.03,5586.09 977.03,5574.09 977.03,5452.09 983.03,5446.09 1453.03,5446.09 1454.03,5447.09
NetC56_2 on Top Layer "TOP_LAYER_NETC56_2_P314" (solid, remove dead copper, pour order 314): 1741.55,5576.11 1852.19,5576.11 1852.19,5462.48 1931,5383.67 1931,5037.56 1874.55,4981.11 1874.55,4693.76 2082.99,4485.33 2082.99,4311.86 2070.24,4299.11 1971.55,4299.11 1971.55,4417.11 1794,4594.67 1794,5057.87 1816,5079.87 1816,5390.67 1781.55,5425.11 1742.55,5425.11
NetC56_1 on Top Layer "TOP_LAYER_NETC56_1_P313" (solid, remove dead copper, pour order 313): 1588.31,5315 1588.31,5132.97 1588.31,5051.96 1674.31,4965.97 1674.31,4490.31 1499.44,4315.44 1426.84,4315.44 1379,4363.28 1379,4562 1592.31,4775.31 1592.31,4936.97 1442.31,5086.97 987.31,5086.97 980.31,5093.97 980.31,5210.97 984.31,5214.97 1116.31,5214.97 1185.31,5283.97 1425.31,5283.97 1456.35,5315
PGND on Top Layer "TOP_LAYER_PGND_P311" (solid, remove dead copper, pour order 311): 1994,4887 2364,4887 2531,4720 2531,4037 2094,3600 1531,3600 1531,3803 2053,3803 2281,4031 2281,4691 2171,4801 1994,4801
PGND on Top Layer "TOP_LAYER_PGND_P295" (solid, remove dead copper, pour order 295): 3840,2722 3797,2679 3797,2501 3964,2501 3964,2401 4025,2401 4050,2426 4050,2501 4251,2501 4251,2722
VM on Top Layer "TOP_LAYER_VM_P293" (solid, remove dead copper, pour order 293): 4324,3204 4235.92,3204 4233.92,3202 4233.92,3175.08 4236,3173 4324,3173
GND on Top Layer "TOP_LAYER_GND_P291" (solid, remove dead copper, pour order 291): 5016,5556 5197,5556 5197,5757 5016,5757
GND on Top Layer "TOP_LAYER_GND_P272" (solid, remove dead copper, pour order 272): 4951,4162 6069,4162 6069,4300 4951,4300
PGND on Top Layer "TOP_LAYER_PGND_P166" (solid, remove dead copper, pour order 166): 500,1724 854,1724 854,2750 3171,2750 3308,2613 3308,2084 3309,2085 3319,2085 3623.5,2389.5 3623.5,2992.5 3663,2992.5 3663,3040.23 3666.77,3044 3851,3044 3851,2980 4223,2980 4223,3037.95 4223.03,3009 4670,3009 4670,3206 4423,3206 4423,3155.24 4361.76,3094 4199,3094 4155.18,3123 4155.18,3195 3918.96,3195 3918.96,3123.81 3875,3094 3851,3094 3650,3094 3557,3001 500,3001
BK_OUT on Top Layer "TOP_LAYER_BK_OUT_P148" (solid, remove dead copper, pour order 148): 2208,933.44 2341,933.44 2342,934.44 2342,1200.44 2287,1255.44 2200,1255.44 2200,1220.28 2199.72,1220 2221,1220 2221,1010.44 2208,983.44
3V3 on Top Layer "TOP_LAYER_3V3_P102" (solid, remove dead copper, pour order 102): 2312,1628 2312,1850 2314,1852 2315,1851 2434,1851 2434,1629 2433,1628
GVDD on Top Layer "TOP_LAYER_GVDD_P004" (solid, remove dead copper, pour order 4): 3846,3045 3847,3046 3684,3046 3628,2990 3628,2799 3539,2710 3539,2330 3437,2228 1132,2228 1016,2112 1016,1858 1147,1727 1759,1727 2106,2074 3391,2074 3616,2299 3616,2688 3701,2773 3701,2941 3700,2942 3780,3022 3846,3022
OUTA on Top Layer "TOP_LAYER_OUTA_P086" (solid, remove dead copper, pour order 86): 3907.6,3276 3913,3281.4 3913,3410 3818.85,3504.15 3672.85,3504.15 3604,3573 3604,3867 3631,3894 3631,4364 3391,4364 3311,4284 3311,3605.42 3640.42,3276
NetC28_1 on Top Layer "TOP_LAYER_NETC28_1_P060" (solid, remove dead copper, pour order 60): 2289,1479.44 2304,1494.44 2304,1665.44 2299,1670.44 2250,1670.44 2246,1666.44 2246,1507.44 2245,1506.44 2245,1496.44 2264,1477.44 2288.85,1477.44
VREF_IN on Top Layer "TOP_LAYER_VREF_IN_P044" (solid, remove dead copper, pour order 44): 2150.62,1409.44 2123,1381.82 2123,1338 2191.56,1269.44 2239,1269.44 2239,1268.44 2262,1245.44 2316,1245.44 2316,1343.3 2289,1370.3 2289,1409.44
NetC2_1 on Top Layer "TOP_LAYER_NETC2_1_P040" (solid, remove dead copper, pour order 40): 2231,817.44 2262,848.44 2339.43,848.44 2342,851.02 2342,901.44 2208,901.44 2208,785.44 2231,785.44
NetC7_1 on Top Layer "TOP_LAYER_NETC7_1_P038" (solid, remove dead copper, pour order 38): 2193,785.44 2171,785.44 2142,814.44 2142,1057.44 2122,1077.44 2122,1134.48 2147.04,1159.44 2180,1159.44 2207,1132.44 2207,994.44 2193,980.44
OUT_C on Top Layer "TOP_LAYER_OUT_C_P028" (solid, remove dead copper, pour order 28): 4521,4437 4644,4437 4644,5163 4537,5270 4385,5270 4385,4573
OUT_A on Top Layer "TOP_LAYER_OUT_A_P024" (solid, remove dead copper, pour order 24): 3567,4440 3459,4440 3459,4684 3490,4715 3490,5214 3552,5276 3742,5276 3742,4617.69 3566,4441.69
OUT_B on Top Layer "TOP_LAYER_OUT_B_P020" (solid, remove dead copper, pour order 20): 4172.69,4439 4173.69,4440 4172,4441.69 4172,5273.09 3950.09,5273.09 3938,5261 3938,4519 4018,4439
OUTB on Top Layer "TOP_LAYER_OUTB_P018" (solid, remove dead copper, pour order 18): 4099.57,3278 3974,3278 3974,3494 3770,3698 3770,4199 3944,4373 4270,4373 4270,3682 4042,3454 4042,3445.16 4098.26,3445.16
OUTC on Top Layer "TOP_LAYER_OUTC_P014" (solid, remove dead copper, pour order 14): 4159,3276 4159,3409 4161,3411 4162,3410 4182.78,3410 4182.78,3441.93 4256,3515.15 4314.15,3515.15 4408,3609 4408,4261.23 4524.77,4378 4627,4378 4708,4297 4708,3469 4515,3276
SLA on Top Layer "TOP_LAYER_SLA_P010" (solid, remove dead copper, pour order 10): 4003,3086 4003,2925 3972,2894 3972,2784 3884,2784 3884,2882 3919,2917 3954,2952 3954,3086
SLB on Top Layer "TOP_LAYER_SLB_P008" (solid, remove dead copper, pour order 8): 4060,3086 4061,3085 4061,2923 4080.86,2903.14 4080.86,2782 3991.53,2782 3991.53,2902.53 4012,2923 4012,3086
SLC on Top Layer "TOP_LAYER_SLC_P006" (solid, remove dead copper, pour order 6): 4120,2944.87 4193,2871.87 4193,2783 4100.54,2783 4100.54,2893.46 4071,2923 4071,3086 4120,3086
NetF2_1 on Bottom Layer "BOTTOM_LAYER_NETF2_1_P326" (solid, remove dead copper, pour order 326): 1284,3967 1284,4098 998,4384 876,4384 782,4290 782,3969 1280,3969 1282,3967
NetD7_1 on Bottom Layer "BOTTOM_LAYER_NETD7_1_P321" (solid, remove dead copper, pour order 321): 1472.18,4823.72 1472.18,4855.14 1472.18,4859.82 1422.28,4909.72 952.18,4909.72 889.18,4846.72 889.18,4562.72 1154.18,4562.72 1388.18,4796.72 1445.18,4796.72 1449.18,4800.72
GND on Bottom Layer "BOTTOM_LAYER_GND_P316" (solid, remove dead copper, pour order 316): 5016,5811 5017,5810 5017,5563 6072,5563 6228,5407 6228,3035.8 6227,3034.8 6226.8,3035 6076,3035 6076,4302 4958,4302 4958,4169 5609,4169 5609,3262 5430,3083 4824,3083 4824,1891 4643,1710 4642.42,1710.58 3321.42,1710.58 3174,1858 3174,2636 3070,2740 855,2740 855,451.18 1261.18,45 6375,45 6375,5440 6137,5678 6137,5788 6131,5794 6131,5805 6127,5809 6105.44,5809
NetF1_2 on Bottom Layer "BOTTOM_LAYER_NETF1_2_P307" (solid, remove dead copper, pour order 307): 1452,5588 987,5588 975,5576 975,5454 981,5448 1451,5448 1452,5449
NetC56_2 on Bottom Layer "BOTTOM_LAYER_NETC56_2_P308" (solid, remove dead copper, pour order 308): 1742,5576 1852.64,5576 1852.64,5462.36 1931,5384 1931,5037 1875,4981 1875,4693.65 2083.44,4485.22 2083.44,4311.75 2070.69,4299 1972,4299 1972,4417 1794,4595 1794,4959.5 1794,5057.31 1817,5080.31 1817,5390 1782,5425 1743,5425
NetC56_1 on Bottom Layer "BOTTOM_LAYER_NETC56_1_P306" (solid, remove dead copper, pour order 306): 1587,5315 1587,5133 1587,5052 1673,4966 1673,4495.59 1492.88,4315.47 1425.53,4315.47 1380,4361 1380,4562.28 1591,4773.28 1591,4937 1441,5087 986,5087 979,5094 979,5211 983,5215 1115,5215 1184,5284 1424,5284 1455,5315
PGND on Bottom Layer "BOTTOM_LAYER_PGND_P310" (solid, remove dead copper, pour order 310): 1994,4887 2365,4887 2531,4721 2531,4039 1854,3362 1531,3362 1531,3803 1944,3803 2280,4139 2280,4692 2171,4801 1994,4801
OUT_C on Bottom Layer "BOTTOM_LAYER_OUT_C_P305" (solid, remove dead copper, pour order 305): 4381.4,5277 4555,5277 4555,5203 4553,5201 4381.4,5201
OUT_A on Bottom Layer "BOTTOM_LAYER_OUT_A_P304" (solid, remove dead copper, pour order 304): 3572.4,5278 3746,5278 3746,5204 3744,5202 3572.4,5202
OUT_B on Bottom Layer "BOTTOM_LAYER_OUT_B_P303" (solid, remove dead copper, pour order 303): 3950.4,5277 4124,5277 4124,5203 4122,5201 3950.4,5201
PGND on Bottom Layer "BOTTOM_LAYER_PGND_P266" (solid, remove dead copper, pour order 266): 3148,2775 3308,2615 3308,1837 4665,1837 4665,3206 3308,3206 3308,3004 1751,3004 1751,3255 2535,4039 2535,4554 3248,5267 3368,5387 4444,5387 4521,5387 4521,5435 2942,5435 2280,4773 2280,4131 1532,3383 1532,3004 503,3004 503,2127 820,2127 820,2775
OUTC on Bottom Layer "BOTTOM_LAYER_OUTC_P078" (solid, remove dead copper, pour order 78): 4706,4176 4619,4263 4457,4263 4410,4216 4410,3569 4357,3516 4256.12,3516 4183,3442.88 4183,3410.19 4160,3410.19 4160,3274 4512,3274 4706,3468
OUTB on Bottom Layer "BOTTOM_LAYER_OUTB_P076" (solid, remove dead copper, pour order 76): 4099.85,3278 3970.19,3278 3970.19,3489.81 3796,3664 3796,4217 3950,4371 4277,4371 4277,3660 4099.85,3482.85
OUTA on Bottom Layer "BOTTOM_LAYER_OUTA_P016" (solid, remove dead copper, pour order 16): 3913,3276 3913,3410 3893.48,3410.09 3893.48,3440.39 3825.86,3508 3666.43,3508 3603,3571.43 3603,3866 3631,3894 3631,4364 3391,4364 3311,4284 3311,3582 3606,3287 3795,3287 3795,3276
3V3 on Power "POWER_3V3_P100" (solid, remove dead copper, pour order 100): 2312,1628 2356,1628 2420,1564 2420,1495 3505,1495 4893,107 6086,1300 6086,2771 4453.5,1138.5 4264,1328 4264,1786 5086,2608 5086,3130 4607,3130 4607,2917 4311,2621 4311,2201 4016,1906 3668,1906 3614,1852 2312,1852

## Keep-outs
Keep-Out Layer:
  text ".Layer_Name" at 860.77,-1220.79 h35

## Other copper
Top Layer:
  rectangle net PGND: 4477,3174 4510,3203.7
  text ".Layer_Name" at 860.77,-1220.79 h60
Bottom Layer:
  text ".Layer_Name" at 860.77,-1220.79 h60

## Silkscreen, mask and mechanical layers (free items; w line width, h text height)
Top Overlay:
  lines w10: 2384,5616 2372,5628 2372,5629 2372,5633 ; 2432,5633 2414,5633 2372,5633 ; 2581.22,5508.39 ccw(c2546,5506.68) 2581.26,5506.71 ; 2753.22,5507.71 ccw(c2718,5506) 2753.26,5506.03 ; 2930.96,5506.68 ccw(c2895.74,5504.97) 2931,5505 ; 2372,5633 2384,5645 2372,5633 ; 2436,5379 3001,5379 3001,5755.36 2998.64,5753 2436,5753 2436,5379
  text "5A ABS MAX" at 3901,5756 h50
  text "5A ABS MAX" at 913,5664 h50
  text "OUT_A" at 3579,5610 h50
  text "OUT_B" at 3976,5608 h50
  text "OUT_C" at 4396,5606.02 h50
  text "PE" at 2792.75,5590.43 h72.83
  text "+" at 2463.51,5579.43 h100
  text "-" at 2638.51,5573.43 h100
  text "PWR" at 5273,5492 h50
  text "HALLA" at 5450,5492 h50
  text "HALLB" at 5661,5492 h50
  text "HALLC" at 5864,5492 h50
  text "GND" at 6081,5492 h50
  text "EXT_PWR" at 6157,5380 h50
  text "EXT" at 5999,5361 h50 r90
  text "3.3V" at 5614,5358 h50 r90
  text "+" at 1334.43,5283.97 h50
  text "BRAKE" at 4987,2489 h35
  text "GND" at 4893.61,2487.19 h35
  text "HALLB" at 5616,2482 h35
  text "PGND" at 963,2284 h35
  text "GVDD" at 961.31,2177.02 h35
  text "INHA" at 4944.82,2013 h35 r90
  text "INLA" at 5044.82,2013 h35 r90
  text "INHB" at 5147.97,2012 h35 r90
  text "INLB" at 5246.82,2010 h35 r90
  text "INHC" at 5346.82,2007 h35 r90
  text "INLC" at 5446.82,2007 h35 r90
  text "HALLC" at 5542.82,1981 h35 r90
  text "5V/ns" at 3186,1881 h50
  text "10V/ns" at 3188,1759 h50
  text "GVDD" at 3449,1753 h50
  text "3.3V" at 3619,1752 h50
  text "20V/ns" at 3183,1654 h50
  text "40V/ns" at 3185,1558 h50
  text "GND" at 3824.45,1124.5 h50 r90
  text "ISENC" at 5748.11,1085.77 h35 r90
  text "ISENB" at 5647.11,1084.77 h35 r90
  text "VSENA" at 5147.82,1084 h35 r90
  text "VSENC" at 5332.43,1084 h35 r90
  text "VSENVM" at 5420.66,1084 h35 r90
  text "ISENA" at 5565.82,1084 h35 r90
  text "VSENB" at 5244.82,1083 h35 r90
  text "R73/R74" at 4184.82,1061 h50 r90
  text "3.3V" at 4930.7,320.69 h35 r90
  text "HALLC" at 5242.53,282.59 h35 r90
  text "nFAULT" at 5630.82,267.8 h35 r90
  text "ENABLE" at 5340.7,256.69 h35 r90
  text "VTEMP_IN" at 5060.84,231 h35 r90
  text ".Layer_Name" at 860.77,-1220.79 h35
Bottom Overlay:
  text ".Layer_Name" at 860.77,-1220.79 h35
Top Paste:
  text ".Layer_Name" at 860.77,-1220.79 h35
Bottom Paste:
  text ".Layer_Name" at 860.77,-1220.79 h35
Top Solder:
  text ".Layer_Name" at 860.77,-1220.79 h35
  text ".Layer_Name" at 860.77,-1220.79 h35
Bottom Solder:
  text ".Layer_Name" at 860.77,-1220.79 h35
Drill Guide:
  text ".Layer_Name" at 860.77,-1220.79 h35
M1 Board Outline:
  lines w10: 0,0 0,5223 ; 3253.32,-784.8 3253.77,-784.34 ; 473,0 473,6000 ; 473,0 6660,0 6660,6000 473,6000 ; 473,0 473,6000
  text ".Layer_Name" at 860.77,-1220.79 h35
